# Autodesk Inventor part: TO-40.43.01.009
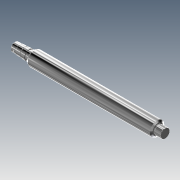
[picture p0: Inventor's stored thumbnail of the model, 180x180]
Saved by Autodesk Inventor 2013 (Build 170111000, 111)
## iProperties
Shininess: 86.0
Length Units: 11269
Angle Units: 11279
Time Units: 11290
Mass Units: 11283
Length Display Precision: 3
Angle Display Precision: 2
Created: 2001-11
Part Number: TO-40.43.01.009
Material: Steel, Mild
Document SubType Name: Modeling
Designer: SOleg
Density: 7.86 g/cm^3
Density: 0.0
Volumn: 0.0
Area: 0.0
PropertySet Name: Model Information
Control State: 0
Master: False
Checked Out: False
Checked Out Date: 2008-10-09
Last Check In Date: 2008-10-09
Author: SOleg
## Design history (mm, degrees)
body "Solid1"
node "WorkPlane2"
node "WorkPlane1"
sketch "Sketch3"
  geometry: L1 (512.5, 27.5)-(512.5, -27.5) reference; L2 (512.5, 34.226)-(512.5, -34.226) reference; C1 r 4 at (598.5, 0)
  constraints: 1 centre point
  dimensions: "d70" = 8 diameter of C1; "d76" = 86 distance from line of L2 C1.centre
extrude "ExtrusionMidplane2" cut sketch "Sketch3" stored distance "d71" = 60; taper "d72" = 0 deg
revolve "RevolutionAngle1" stored, may be unused: angle "d56" = 360 deg
node "WorkAxis1"
chamfer "Chamfer1" distance "d57" = 10; stored, may be unused: angle "d58" = 28 deg, second distance "d74" = 10
chamfer "Chamfer2" distance "d59" = 10; stored, may be unused: angle "d60" = 30 deg, second distance "d75" = 10
sketch "Sketch1"
  geometry: L1 (-614.5, 22)-(-614.5, 0); L2 (-612.5, 24)-(-614.5, 22); L3 (-586.5, 24)-(-612.5, 24); L4 (-584.5, 26)-(-586.5, 24); L5 (-561, 26)-(-584.5, 26); L6 (-559.5, 24.5)-(-561, 26); L7 (-554.5, 24.5)-(-559.5, 24.5); L8 (-554.5, 26.5)-(-554.5, 24.5); L9 (-553.5, 27.5)-(-554.5, 26.5); L10 (-534.1, 27.5)-(-553.5, 27.5); L11 (-534.1, 23.8)-(-534.1, 27.5); L12 (-528.5, 23.8)-(-534.1, 23.8); L13 (-528.5, 27.5)-(-528.5, 23.8); L14 (-512.5, 27.5)-(-528.5, 27.5); L15 (-512.5, 40)-(-512.5, 27.5); L16 (179.5, 40)-(-512.5, 40); L17 (179.5, 24)-(179.5, 40); L18 (184.5, 24)-(179.5, 24); L19 (186.5, 26)-(184.5, 24); L20 (217.5, 26)-(186.5, 26); L21 (219.5, 24)-(217.5, 26); L22 (219.5, 0)-(219.5, 24); L23 (-614.5, 0)-(219.5, 0); L24 (-614.5, 0)-(219.5, 0)
  constraints: 48 end point, 8 horizontal, 5 vertical
  dimensions: "d1" = 2 horizontal distance of L21.start L20.start; "d3" = 2 horizontal distance of L21.start L20.start; "d5" = 2 horizontal distance of L19.start L18.start; "d7" = 2 horizontal distance of L19.start L18.start; "d9" = 40 horizontal distance of L22.start L16.start; "d11" = 5 distance of L18.start L17.start; "d13" = 40 distance of L17.start L21.start; "d15" = 26 vertical distance of L19.start L22.start; "d17" = 834 distance of L1.end L22.start; "d19" = 16 distance of L14.start L13.start; "d21" = 27.5 vertical distance of L13.start L1.end; "d23" = 23.8 vertical distance of L12.start L1.end; "d25" = 27.5 vertical distance of L10.start L1.end; "d27" = 5.6 distance of L12.start L11.start; "d29" = 2 horizontal distance of L2.start L1.start; "d31" = 2 horizontal distance of L2.start L1.start; "d33" = 1 horizontal distance of L9.start L8.start; "d35" = 1 horizontal distance of L9.start L8.start; "d37" = 24.5 vertical distance of L7.start L1.end; "d39" = 26 vertical distance of L4.start L1.end; "d41" = 5 distance of L7.start L6.start; "d43" = 135 deg angle of L7 L6; "d45" = 2 horizontal distance of L4.start L3.start; "d47" = 2 horizontal distance of L4.start L3.start; "d49" = 28 horizontal distance of L1.start L3.start; "d51" = 60 horizontal distance of L1.start L7.start; "d53" = 26 vertical distance of L5.start L1.end; "d55" = 102 horizontal distance of L1.end L15.start
other parameters: "d0" = 2 (derived), "d2" = 2 (derived), "d4" = 2 (derived), "d6" = 2 (derived), "d10" = 5 (derived), "d14" = 26 (derived), "d16" = 629 (derived), "d18" = 16 (derived), "d20" = 27.5 (derived), "d22" = 23.8 (derived), "d24" = 27.5 (derived), "d26" = 5.6 (derived), "d28" = 2 (derived), "d30" = 2 (derived), "d32" = 1 (derived), "d34" = 1 (derived), "d36" = 24.5 (derived), "d38" = 26 (derived), "d40" = 5 (derived), "d42" = 135 deg (derived), "d44" = 2 (derived), "d46" = 2 (derived), "d48" = 28 (derived), "d52" = 26 (derived), "d54" = 102 (derived), "d61" = 65 (derived), "d69" = 8 (derived)
